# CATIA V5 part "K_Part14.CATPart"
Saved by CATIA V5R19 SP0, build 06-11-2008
Part number: Part14
Bounding box of the stored display mesh (mm): x -45 to 45, y 23.28 to 74.268, z -692 to -659.6
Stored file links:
  G:\Khaled_CFAO_2011\SIL\SIL_GR2\ctanaphiko\Khaled\CAD_ThinkMOTION\K_Part14.CATPart
  G:\Khaled_CFAO_2011\SIL\SIL_GR2\ctanaphiko\CATIA\Conception_Tripod.CATProduct
  G:\Khaled_CFAO_2011\SIL\SIL_GR2\ctanaphiko\CATIA\Squelette.CATPart
  G:\Khaled_CFAO_2011\SIL\SIL_GR2\ctanaphiko\Khaled\CAD_ThinkMOTION\K_Leg_Level1.CATPart
  G:\Khaled_CFAO_2011\SIL\SIL_GR2\ctanaphiko\Khaled\CAD_ThinkMOTION\K_Leg_Level2.CATPart
  G:\Khaled_CFAO_2011\SIL\SIL_GR2\ctanaphiko\Khaled\CAD_ThinkMOTION\K_Part4.CATPart
  G:\Khaled_CFAO_2011\SIL\SIL_GR2\ctanaphiko\Khaled\CAD_ThinkMOTION\K_Part8.CATPart
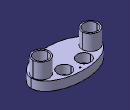
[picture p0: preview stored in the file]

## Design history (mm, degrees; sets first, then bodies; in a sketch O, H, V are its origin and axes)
Parameters
  LENGTH = 18 mm
External parameters (linked from other documents)
  External.Dia_Leg_Step1 = 18 mm
  External.Dia_Leg_Step2 = 18 mm
  External.Dia_Leg_Step3 = 14.3 mm
  External.Width_Leg_Support = 75 mm
  External.Length_Leg1 = 680 mm
AxisSystem1: origin (0, 0, 0), X (1, 0, 0), Y (0, 1, 0), Z (0, 0, 1)
Set1
  Plane1: linked copy from another document
  DatumPoint1: linked copy from another document
  DatumPoint2: linked copy from another document
  DatumCurve1 to DatumCurve4: linked copy from another document
  Plane2 "Plan_S1": linked copy from another document
  Sketch1, origin (0, 0, -68), H (1, 0, 0), V (0, 1, 0), geometry linked from another document
  DatumCurve5: linked copy from another document
Body1 (main body)
  DatumPoint3
  Sketch2 on Plane1, origin (0, 0, -680), H (1, 0, 0), V (0, 1, 0)
    point P1 (0, 48.774)
    construction line L1 (45, 48.774) -> (-45, 48.774)
    point P2 (45, 48.774)
    point P3 (-45, 48.774)
    projected circle E1 centre (13.2127, 61.024) radius 9 from edge of DatumCurve4
    construction line L2 (170.7589, 48.774) -> (122.2057, 48.774)
    construction line L3 (17.1663, 52.024) -> (72.7367, 52.024)
    ellipse A1 centre (0, 48.774) semi-axes 45, 25.5 rotation 0
    point P9 (-45, 48.774)
    projected circle E2 centre (0, 69.024) radius 1 from Sketch1
    projected circle E3 centre (-13.2127, 61.024) radius 9 from edge of DatumCurve5
    construction line L4 (-13.2127, 70.024) -> (-13.2127, 52.024)
    point P10 (-13.2127, 70.024)
    point P11 (-13.2127, 52.024)
    construction line L5 (13.2127, 70.024) -> (13.2127, 52.024)
    point P12 (13.2127, 70.024)
    point P13 (13.2127, 52.024)
    construction line L6 (0, 74.274) -> (0, 23.274)
    point P14 (0, 74.274)
    point P15 (0, 23.274)
    "Radius" A1 = 45 {= External.Width_Leg_Support /2*1.2}
    "Radius" A1 = 25.5 {= External.Dia_Leg_Step1 /2+External.Dia_Leg_Step2 /2+External.Width_Leg_Support /10}
    length L4 = 18 {= External.Dia_Leg_Step2}
    length L5 = 18 {= External.Dia_Leg_Step2}
    length L6 = 51 {= Sketch2.Radius(A1) *2}
    length L1 = 90 {= Sketch2.Radius(A1) *2}
    distance E2 A1 = 4.25 {= Sketch2.Radius(A1) *1/6}
    midpoint: P1 L1
    horizontal: L3 H
    parallelism: A1 L3
    coincidence: P9 L2, A1 P9, P10 E3, P11 E3, P12 E1, P13 E1, L3 P13, P14 A1, P15 A1, L6 V, P3 A1, P2 A1
    vertical: L4 V, L5 V, L6 V
  Pad1: profile Sketch2, direction (0, 0, -1), length 12
  Body2
    Sketch3 on Plane1, origin (0, 0, -680), H (1, 0, 0), V (0, 1, 0)
      projected circle E1 centre (33.0316, 49.774) radius 9 from edge of DatumCurve2
      projected circle E2 centre (-33.0316, 49.774) radius 9 from edge of DatumCurve1
      circle A1 centre (-33.0316, 49.774) radius 10.8
      point P1 (-33.0316, 49.774)
      circle A2 centre (33.0316, 49.774) radius 10.8
      point P2 (33.0316, 49.774)
      radius A2 = 10.8 {= (External.Dia_Leg_Step1 /2)*1.2}
      radius E1 = 9 (reference)
      radius A1 = 10.8 {= (External.Dia_Leg_Step1 /2)*1.2}
      concentricity: P1 E2, P2 E1
    Pad2: profile Sketch3, direction (0, 0, 1), length 20.4 {= External.Length_Leg1 *0.03}
  Add1: tool Body2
